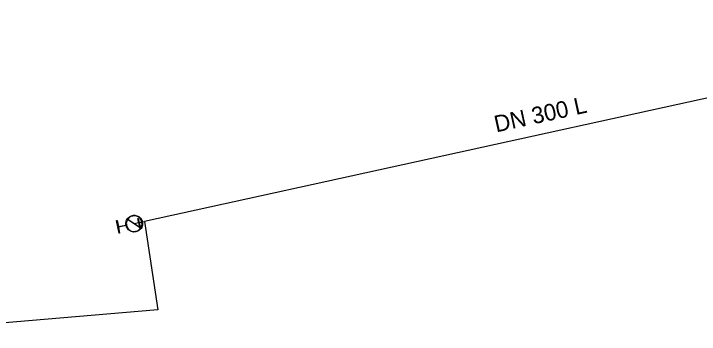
# Model space of a CAD drawing. Extents: x -832382 to -831581, y -1074670 to -1074251.
# Drawn here: x -831872.2 to -831789.8, y -1074321 to -1074282.4 of the extents above; entities that cross this region are included whole.
import ezdxf

# ---------------------------------------------------------------- set-up
doc = ezdxf.new("R2010")
doc.units = 0
for name, color, linetype in [('Hyd-odbočka', 7, 'Continuous'), ('Hyd-šoupě', 7, 'Continuous'), ('Hydrant', 7, 'Continuous'), ('Roz-řad', 7, 'Continuous'), ('Roz-řad-popis základní', 7, 'Continuous')]:
    doc.layers.add(name, color=color, linetype=linetype)

msp = doc.modelspace()

# ---------------------------------------------------------------- linework, layer by layer
at = {"layer": 'Hyd-odbočka'}
for p, q in [((-831857.749, -1074307.649), (-831857.17, -1074307.522)), ((-831857.17, -1074307.522), (-831856.502, -1074307.376))]:
    msp.add_line(p, q, dxfattribs=at)
at = {"layer": 'Hyd-šoupě'}
msp.add_lwpolyline([(-831857.262, -1074307.03), (-831857.048, -1074308.007), (-831857.079, -1074308.014), (-831857.293, -1074307.037), (-831857.262, -1074307.03)], dxfattribs=at)
at = {"layer": 'Hydrant'}
for points in [[(-831858.724, -1074307.875), (-831859.643, -1074308.058), (-831859.497, -1074308.793), (-831859.558, -1074308.806), (-831859.863, -1074307.273), (-831859.802, -1074307.261), (-831859.655, -1074307.997), (-831858.736, -1074307.814)], [(-831856.985, -1074308.196), (-831858.547, -1074307.153)], [(-831858.513, -1074307.102), (-831856.949, -1074308.145)]]:
    msp.add_lwpolyline(points, dxfattribs=at)
for points in [[(-831858.736, -1074307.814), (-831858.774, -1074307.58), (-831858.699, -1074307.336), (-831858.619, -1074307.077), (-831858.41, -1074306.898), (-831858.201, -1074306.719), (-831857.944, -1074306.668), (-831857.689, -1074306.618), (-831857.43, -1074306.7), (-831857.171, -1074306.783), (-831856.995, -1074306.991), (-831856.819, -1074307.199), (-831856.768, -1074307.454), (-831856.718, -1074307.709), (-831856.8, -1074307.968), (-831856.883, -1074308.227), (-831857.091, -1074308.403), (-831857.299, -1074308.579), (-831857.554, -1074308.63), (-831857.81, -1074308.681), (-831858.072, -1074308.596), (-831858.334, -1074308.51), (-831858.507, -1074308.302), (-831858.669, -1074308.107), (-831858.724, -1074307.875)], [(-831856.949, -1074308.145), (-831856.894, -1074308.054), (-831856.861, -1074307.948), (-831856.782, -1074307.705), (-831856.83, -1074307.466), (-831856.877, -1074307.227), (-831857.042, -1074307.031), (-831857.208, -1074306.836), (-831857.45, -1074306.759), (-831857.693, -1074306.682), (-831857.932, -1074306.73), (-831858.173, -1074306.778), (-831858.369, -1074306.946), (-831858.452, -1074307.018), (-831858.513, -1074307.102)], [(-831858.547, -1074307.153), (-831858.605, -1074307.248), (-831858.64, -1074307.356), (-831858.715, -1074307.6), (-831858.668, -1074307.832), (-831858.622, -1074308.064), (-831858.46, -1074308.26), (-831858.297, -1074308.457), (-831858.052, -1074308.537), (-831857.807, -1074308.617), (-831857.566, -1074308.568), (-831857.327, -1074308.521), (-831857.133, -1074308.355), (-831857.047, -1074308.284), (-831856.985, -1074308.196)]]:
    msp.add_open_spline(points, degree=3, dxfattribs=at)
at = {"layer": 'Roz-řad'}
msp.add_line((-831742.483, -1074282.374), (-831856.502, -1074307.376), dxfattribs=at)
msp.add_lwpolyline([(-831856.502, -1074307.376), (-831854.913, -1074318.027), (-831889.348, -1074320.969)], dxfattribs=at)

# ---------------------------------------------------------------- texts
at = {"layer": 'Roz-řad-popis základní'}
msp.add_text('DN 300 L', height=2, rotation=12.36804, dxfattribs=at).set_placement((-831814.196, -1074296.673))

doc.saveas('drawing.dxf')
